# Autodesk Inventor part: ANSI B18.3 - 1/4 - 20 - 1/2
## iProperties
Comments: To add or edit properties for Autodesk Inventor files, use iProperties.
Created: 2004-08
Part Number: ANSI B18.3 - 1/4 - 20 - 1/2
Vendor: Autodesk Inc.
Document SubType Name: Modeling
Designer: John Blackburn
Material: Default
Description: Hexagon Socket Head Cap Screw
Standard: ANSI B18.3
Alert: To add or edit properties for Autodesk Inventor files, use iProperties.
Control State: 0
Master: False
Checked Out: False
Shininess: 64.0
Length Units: 11272
Angle Units: 11279
Time Units: 11290
Mass Units: 11286
Length Display Precision: 3
Angle Display Precision: 2
Compacted: True
EGR: 3
Classification: un/spsc 31161501
Density: 0.0
Volumn: 0.0
Area: 0.0
PropertySet Name: Model Information
Author: John Blackburn
Revision Number: 8
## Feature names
1. Body [Revolution]
2. Slot [Extrusion]
3. Fillet1
4. Chamfer1
